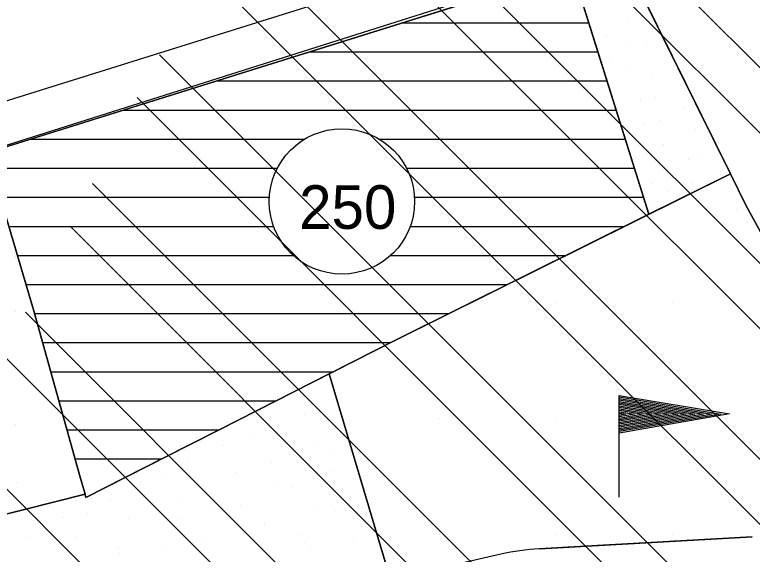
# Model space of a CAD drawing. Extents: x 409341 to 428634, y 4447481 to 4463281.
# Drawn here: x 420653.1 to 420906.8, y 4458343.9 to 4458529.4 of the extents above; entities that cross this region are included whole.
import ezdxf

# ---------------------------------------------------------------- set-up
doc = ezdxf.new("R2010")
doc.units = 0
for name, color, linetype in [('ADA', 7, 'Continuous'), ('ADAKENARI', 7, 'Continuous'), ('Default', 7, 'Continuous'), ('LJ_SEMBOL', 7, 'Continuous'), ('OSB', 7, 'Continuous'), ('PL_AYA_PARK_DINLENME', 7, 'Continuous'), ('PL_EĞİTİM', 7, 'Continuous'), ('PL_KON_ONE_250', 7, 'Continuous'), ('PL_SAY_SPOR', 7, 'Continuous'), ('SM_DAIRE', 7, 'Continuous'), ('SM_TAKS', 7, 'Continuous'), ('SN_TR_SIVILASMA', 7, 'Continuous'), ('TR_EĞİTİM', 7, 'Continuous'), ('TR_KENTSELSPOR', 7, 'Continuous'), ('TR_ORTAGELISME', 7, 'Continuous'), ('TR_PARKALANI', 7, 'Continuous')]:
    doc.layers.add(name, color=color, linetype=linetype)

# ---------------------------------------------------------------- blocks, each defined once
blk = doc.blocks.new('POINT_DISPLAY')
at = {"layer": 'Default'}
blk.add_line((0, 0), (0, 0), dxfattribs=at)

msp = doc.modelspace()

# ---------------------------------------------------------------- linework, layer by layer
at = {"layer": 'ADA'}
for p, q in [((420844.74, 4458545.31), (420871.21, 4458460.84)), ((420643.44, 4458481.99), (420732.53, 4458509.85)), ((420783.99, 4458417.5), (420899.22, 4458474.76)), ((420677.56, 4458363.39), (420783.99, 4458417.5)), ((420782.34, 4458335.03), (420761.16, 4458405.89))]:
    msp.add_line(p, q, dxfattribs=at)
for points in [[(420643.44, 4458481.99), (420659.49, 4458427.94), (420675.59, 4458370.42), (420677.32, 4458364.26), (420677.56, 4458363.39)], [(420623.66, 4458351.01), (420677.24, 4458364.55)]]:
    msp.add_lwpolyline(points, dxfattribs=at)
at = {"layer": 'ADAKENARI'}
for p, q in [((420847.49, 4458561.51), (420577.09, 4458476.96)), ((420732.53, 4458509.85), (420847.49, 4458545.79)), ((420906.76, 4458349.81), (420847.49, 4458346.51)), ((420847.49, 4458346.51), (420833.53, 4458345.74)), ((420820.25, 4458343.88), (420651.06, 4458305.46))]:
    msp.add_line(p, q, dxfattribs=at)
msp.add_arc((420837.97, 4458265.86), 80, 93.1798, 102.7916, dxfattribs=at)
at = {"layer": 'LJ_SEMBOL'}
msp.add_line((420860.99, 4458363.5), (420860.99, 4458398.5), dxfattribs=at)
for points in [[(420860.99, 4458398.5), (420898.94, 4458392.12), (420860.99, 4458385.55)], [(420860.99, 4458397.99), (420895.96, 4458392.11), (420860.99, 4458386.06)], [(420860.99, 4458397.49), (420892.99, 4458392.11), (420860.99, 4458386.56)], [(420860.99, 4458396.98), (420890.02, 4458392.1), (420860.99, 4458387.07)], [(420860.99, 4458396.47), (420887.05, 4458392.09), (420860.99, 4458387.58)], [(420860.99, 4458395.97), (420884.07, 4458392.09), (420860.99, 4458388.09)], [(420860.99, 4458395.46), (420881.1, 4458392.08), (420860.99, 4458388.59)], [(420860.99, 4458394.95), (420878.13, 4458392.07), (420860.99, 4458389.1)], [(420860.99, 4458394.45), (420875.16, 4458392.06), (420860.99, 4458389.61)], [(420860.99, 4458393.94), (420872.18, 4458392.06), (420860.99, 4458390.12)], [(420860.99, 4458393.43), (420869.21, 4458392.05), (420860.99, 4458390.62)], [(420860.99, 4458392.92), (420866.24, 4458392.04), (420860.99, 4458391.13)], [(420860.99, 4458392.42), (420863.27, 4458392.03), (420860.99, 4458391.64)]]:
    msp.add_lwpolyline(points, dxfattribs=at)
at = {"layer": 'OSB'}
msp.add_lwpolyline([(421303.14, 4458521.03), (421213.37, 4458544.99), (420881.63, 4458557.8), (420391.63, 4458402.74)], dxfattribs=at)
at = {"layer": 'PL_AYA_PARK_DINLENME'}
for p, q in [((420899.22, 4458474.76), (420864.13, 4458545.82)), ((420847.49, 4458536.54), (420871.21, 4458460.84)), ((420871.21, 4458460.84), (420899.22, 4458474.76))]:
    msp.add_line(p, q, dxfattribs=at)
msp.add_lwpolyline([(420651.06, 4458305.46), (420782.27, 4458335.25), (420761.16, 4458405.89), (420743.03, 4458396.67), (420723.36, 4458386.67), (420703.69, 4458376.67), (420677.56, 4458363.39), (420677.32, 4458364.26), (420677.24, 4458364.55), (420623.66, 4458351.01), (420632.89, 4458304.12)], dxfattribs=at)
at = {"layer": 'PL_EĞİTİM'}
msp.add_lwpolyline([(420677.24, 4458364.55), (420675.59, 4458370.42), (420659.49, 4458427.94), (420643.44, 4458481.99), (420642.58, 4458484.9), (420639.77, 4458484.06), (420599.65, 4458473.08), (420623.66, 4458351.01), (420677.24, 4458364.55)], dxfattribs=at)
at = {"layer": 'PL_KON_ONE_250'}
for points in [[(421199.4, 4458546.37), (421071.94, 4458546.37), (420879.6, 4458554.52), (420872.41, 4458553.58), (420857.15, 4458548.81), (420864.13, 4458545.82), (420899.22, 4458474.76), (420904.7, 4458463.67), (420914.61, 4458445.59)], [(420677.24, 4458364.55), (420677.32, 4458364.26), (420677.56, 4458363.39), (420703.69, 4458376.67), (420723.36, 4458386.67), (420743.03, 4458396.67), (420761.16, 4458405.89), (420783.99, 4458417.5), (420871.21, 4458460.84), (420847.49, 4458536.54), (420844.85, 4458544.96), (420732.53, 4458509.85), (420643.44, 4458481.99), (420659.49, 4458427.94), (420675.59, 4458370.42), (420677.24, 4458364.55)]]:
    msp.add_lwpolyline(points, dxfattribs=at)
at = {"layer": 'PL_SAY_SPOR'}
for p, q in [((420899.22, 4458474.76), (420871.21, 4458460.84)), ((420904.7, 4458463.67), (420899.22, 4458474.76)), ((420871.21, 4458460.84), (420783.99, 4458417.5)), ((420783.99, 4458417.5), (420761.16, 4458405.89)), ((420761.16, 4458405.89), (420782.27, 4458335.25)), ((420833.53, 4458345.74), (420906.76, 4458349.81))]:
    msp.add_line(p, q, dxfattribs=at)
msp.add_lwpolyline([(420970.15, 4458344.23), (420943.04, 4458393.72), (420914.61, 4458445.59), (420904.7, 4458463.67)], dxfattribs=at)
msp.add_arc((420837.97, 4458265.86), 80, 93.1798, 102.7916, dxfattribs=at)
at = {"layer": 'SM_DAIRE'}
msp.add_circle((420765.61, 4458465.23), 25, dxfattribs=at)
at = {"layer": 'SN_TR_SIVILASMA'}
for p, q in [((420847.49, 4458483.35), (420744.42, 4458586.42)), ((420847.49, 4458505.8), (420766.87, 4458586.42)), ((420976.93, 4458443.72), (420847.49, 4458573.15)), ((420847.49, 4458438.45), (420719.15, 4458566.79)), ((420953.78, 4458444.41), (420847.49, 4458550.7)), ((420847.49, 4458416), (420715.58, 4458547.91)), ((420847.49, 4458371.1), (420702.89, 4458515.7)), ((420922.98, 4458430.31), (420847.49, 4458505.8)), ((420847.49, 4458348.64), (420695.19, 4458500.95)), ((421298.05, 4458032.79), (420847.49, 4458483.35)), ((420847.49, 4458303.74), (420679.79, 4458471.44)), ((420847.49, 4458281.29), (420672.1, 4458456.69)), ((421297.58, 4457988.35), (420847.49, 4458438.45)), ((420847.49, 4458236.39), (420656.7, 4458427.18)), ((421297.35, 4457966.14), (420847.49, 4458416)), ((420847.49, 4458213.94), (420649.01, 4458412.43)), ((420847.49, 4458169.04), (420633.61, 4458382.92)), ((421296.89, 4457921.7), (420847.49, 4458371.1)), ((421296.66, 4457899.48), (420847.49, 4458348.64))]:
    msp.add_line(p, q, dxfattribs=at)
at = {"layer": 'TR_ORTAGELISME'}
for p, q in [((420786.35, 4458526.67), (420850.58, 4458526.67)), ((420754.36, 4458516.67), (420853.71, 4458516.67)), ((420722.38, 4458506.67), (420856.85, 4458506.67)), ((420690.4, 4458496.67), (420859.98, 4458496.67)), ((420658.41, 4458486.67), (420752.75, 4458486.67)), ((420778.47, 4458486.67), (420863.11, 4458486.67)), ((420645.85, 4458476.67), (420743.38, 4458476.67)), ((420787.84, 4458476.67), (420866.24, 4458476.67)), ((420648.65, 4458466.67), (420740.65, 4458466.67)), ((420790.57, 4458466.67), (420869.38, 4458466.67)), ((420651.45, 4458456.67), (420742.12, 4458456.67)), ((420789.1, 4458456.67), (420862.83, 4458456.67)), ((420654.25, 4458446.67), (420748.86, 4458446.67)), ((420782.36, 4458446.67), (420842.7, 4458446.67)), ((420657.05, 4458436.67), (420822.58, 4458436.67)), ((420659.84, 4458426.67), (420802.45, 4458426.67)), ((420662.64, 4458416.67), (420782.37, 4458416.67)), ((420665.44, 4458406.67), (420762.7, 4458406.67)), ((420668.24, 4458396.67), (420743.03, 4458396.67)), ((420671.04, 4458386.67), (420723.36, 4458386.67)), ((420673.84, 4458376.67), (420703.69, 4458376.67))]:
    msp.add_line(p, q, dxfattribs=at)
msp.add_lwpolyline([(421199.4, 4458546.37), (421071.94, 4458546.37), (420879.6, 4458554.52), (420872.41, 4458553.58), (420857.15, 4458548.81), (420864.13, 4458545.82), (420899.22, 4458474.76), (420904.7, 4458463.67), (420914.61, 4458445.59)], dxfattribs=at)

# ---------------------------------------------------------------- block references
at = {"layer": 'TR_EĞİTİM', "xscale": 0.1, "yscale": 0.10000000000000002}
for p in [(420653.27, 4458446.19), (420653.27, 4458427.34), (420653.72, 4458407.43), (420653.27, 4458388.63), (420653.72, 4458368.72)]:
    msp.add_blockref('POINT_DISPLAY', p, dxfattribs=at)
at = {"layer": 'TR_KENTSELSPOR', "xscale": 0.1, "yscale": 0.10000000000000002}
for p in [(420839.2, 4458430.55), (420839.2, 4458430.55), (420839.2, 4458430.55), (420839.2, 4458430.55), (420879.2, 4458430.55), (420879.2, 4458430.55), (420879.2, 4458430.55), (420879.2, 4458430.55), (420799.2, 4458390.55), (420799.2, 4458390.55), (420799.2, 4458390.55), (420799.2, 4458390.55), (420839.2, 4458390.55), (420839.2, 4458390.55), (420839.2, 4458390.55), (420839.2, 4458390.55), (420879.2, 4458390.55), (420879.2, 4458390.55), (420879.2, 4458390.55), (420879.2, 4458390.55), (420799.2, 4458350.55), (420799.2, 4458350.55), (420799.2, 4458350.55), (420799.2, 4458350.55), (420839.2, 4458350.55), (420839.2, 4458350.55), (420839.2, 4458350.55), (420839.2, 4458350.55), (420879.2, 4458350.55), (420879.2, 4458350.55), (420879.2, 4458350.55), (420879.2, 4458350.55)]:
    msp.add_blockref('POINT_DISPLAY', p, dxfattribs=at)
at = {"layer": 'TR_PARKALANI', "xscale": 0.1, "yscale": 0.10000000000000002}
for p in [(420863.99, 4458527.14), (420869.19, 4458526.98), (420856.59, 4458522.27), (420863.57, 4458519.08), (420870.22, 4458518.94), (420857.61, 4458514.23), (420864.6, 4458511.04), (420872.38, 4458508.91), (420881.95, 4458505.11), (420868.28, 4458499.95), (420873.41, 4458500.87), (420882.97, 4458497.07), (420869.31, 4458491.91), (420875.11, 4458492.96), (420887.11, 4458489.92), (420876.14, 4458484.93), (420888.14, 4458481.89), (420894.7, 4458482.64), (420884.98, 4458479.75), (420876.78, 4458476.71), (420895.73, 4458474.6), (420871.93, 4458471.4), (420886.01, 4458471.71), (420877.81, 4458468.68), (420872.95, 4458463.36), (420901.41, 4458462.46), (420901.41, 4458462.46), (420904.74, 4458457.87), (420904.74, 4458457.87), (420901.41, 4458454.23), (420901.41, 4458454.23), (420752.76, 4458391.99), (420752.76, 4458391.99), (420735.2, 4458385.02), (420735.2, 4458385.02), (420724.92, 4458381.22), (420724.92, 4458381.22), (420757.11, 4458381.65), (420757.11, 4458381.65), (420761.74, 4458378.6), (420761.74, 4458378.6), (420761.74, 4458378.6), (420761.74, 4458378.6), (420712.43, 4458376.95), (420712.43, 4458376.95), (420741.34, 4458375.28), (420741.34, 4458375.28), (420704.99, 4458371.09), (420704.99, 4458371.09), (420729.16, 4458371.96), (420729.16, 4458371.96), (420761.74, 4458372.23), (420761.74, 4458372.23), (420761.74, 4458372.23), (420761.74, 4458372.23), (420696.14, 4458367.61), (420696.14, 4458367.61), (420742.36, 4458367.24), (420742.36, 4458367.24), (420742.36, 4458367.24), (420742.36, 4458367.24), (420748.73, 4458367.24), (420748.73, 4458367.24), (420748.73, 4458367.24), (420748.73, 4458367.24), (420685.85, 4458362.55), (420685.85, 4458362.55), (420710.26, 4458363.25), (420710.26, 4458363.25), (420720.5, 4458360.32), (420720.5, 4458360.32), (420720.5, 4458360.32), (420720.5, 4458360.32), (420730.7, 4458360.64), (420730.7, 4458360.64), (420730.7, 4458360.64), (420730.7, 4458360.64), (420677.95, 4458357.96), (420677.95, 4458357.96), (420756.2, 4458358.93), (420756.2, 4458358.93), (420756.2, 4458358.93), (420756.2, 4458358.93), (420763.12, 4458358.93), (420763.12, 4458358.93), (420763.12, 4458358.93), (420763.12, 4458358.93), (420660.64, 4458356.65), (420669.77, 4458356.65), (420692.09, 4458356.31), (420692.09, 4458356.31), (420710.25, 4458355.89), (420710.25, 4458355.89), (420710.25, 4458355.89), (420710.25, 4458355.89), (420739.08, 4458353.99), (420739.08, 4458353.99), (420739.08, 4458353.99), (420739.08, 4458353.99), (420656.96, 4458349.86), (420731.84, 4458350.9), (420731.84, 4458350.9), (420731.84, 4458350.9), (420731.84, 4458350.9), (420750.6, 4458350.38), (420750.6, 4458350.38), (420667.82, 4458348.77), (420667.82, 4458348.77), (420674.37, 4458349.54), (420674.37, 4458349.54), (420718.68, 4458349.4), (420718.68, 4458349.4), (420718.68, 4458349.4), (420718.68, 4458349.4), (420752.97, 4458347.99), (420752.97, 4458347.99), (420769.65, 4458348.23), (420769.65, 4458348.23), (420769.65, 4458348.23), (420769.65, 4458348.23), (420688.91, 4458346.03), (420688.91, 4458346.03), (420703.9, 4458346.79), (420703.9, 4458346.79), (420703.9, 4458346.79), (420703.9, 4458346.79), (420754.88, 4458345.63), (420754.88, 4458345.63), (420754.88, 4458345.63), (420754.88, 4458345.63), (420689.13, 4458344.19), (420689.13, 4458344.19), (420689.13, 4458344.19), (420689.13, 4458344.19), (420717.13, 4458344.02), (420717.13, 4458344.02)]:
    msp.add_blockref('POINT_DISPLAY', p, dxfattribs=at)

# ---------------------------------------------------------------- texts
at = {"layer": 'SM_TAKS'}
msp.add_text('250', height=15, dxfattribs=at).set_placement((420750.87, 4458455.79))

doc.saveas('drawing.dxf')
